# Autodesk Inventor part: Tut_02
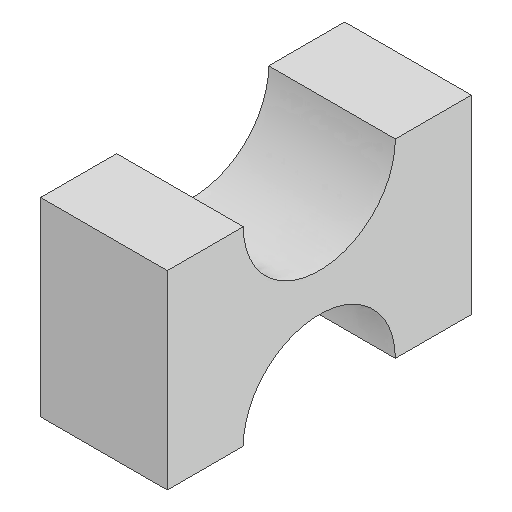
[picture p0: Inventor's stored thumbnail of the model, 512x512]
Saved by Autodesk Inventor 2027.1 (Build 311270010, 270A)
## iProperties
Created: 2022-07
Part Number: Tut_02
Material: Generic
Document SubType Name: Modeling
Designer: LENOVO-CADCIM
Density: 1 g/cm^3
Appearance: Default
Author: LENOVO-CADCIM
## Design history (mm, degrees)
sketch "Sketch5"
  geometry: L1 (0, 0)-(0, 12); L2 (0, 0)-(12, 0); L3 (0, 0)-(0, -12); L4 (0, 12)-(0, 24); L5 (0, 12)-(12, 12); L6 (0, 24)-(-30, 24); L7 (-30, 24)-(-30, 12); L8 (-30, 12)-(-30, -12); L9 (-30, 12)-(-6, 12); L10 (-30, -12)-(-30, -24); L11 (-30, -12)-(-18, -12); L12 (-30, -24)-(0, -24); L13 (0, -24)-(0, -12); L14 (0, -24)-(12, -24); A1 r 12 centre (0, 0) between (0, 12) and (0, -12); A2 r 12 centre (-30, 0) between (-30, -12) and (-30, 12); 1 further point
  constraints: 28 end point, 8 perpendicular, 5 horizontal, 4 point on circle, 2 centre point, 2 vertical, 1 coincident
  dimensions: "d0" = 12 radius of A1; "d1" = 90 deg angle of L2 L1; "d2" = 180 deg angle of L3 L1; "d3" = 12 distance of L1.end L4.end; "d4" = 90 deg angle of L5 L4 (derived); "d5" = 30 distance of L4.end L6.end; "d6" = 90 deg angle of L6 L4 (derived); "d7" = 12 distance of L6.end L7.end; "d8" = 90 deg angle of L7 L6 (derived); "d9" = 24 distance of L7.end L8.end; "d10" = 90 deg angle of L8 L9; "d11" = 12 radius of A2; "d12" = 12 distance of L8.end L10.end; "d13" = 90 deg angle of L10 L11 (derived); "d14" = 30 distance of L10.end L12.end; "d15" = 90 deg angle of L12 L10 (derived); "d16" = 12 distance of L12.end L3.end (derived); "d17" = 90 deg angle of L14 L13 (derived)
extrude "Extrusion1" new body sketch "Sketch5" distance "d18" = 20; taper "d19" = 0 deg
body "Solid1"
